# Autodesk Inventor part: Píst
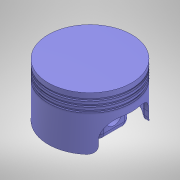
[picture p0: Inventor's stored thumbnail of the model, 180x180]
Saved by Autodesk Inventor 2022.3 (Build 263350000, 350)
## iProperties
Created: 2025-11
Part Number: Píst
Material: Všeobecné
Document SubType Name: Modeling
Designer: Hra42
Density: 1 g/cm^3
Appearance: Výchozí
Author: Hra42
Sending System: SolidWorks 2012
Last Author: Hra42
Last Saved: 2025-11-14
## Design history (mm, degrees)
feature "T_X2_011B_X0_leso1"
node "Těleso1"
